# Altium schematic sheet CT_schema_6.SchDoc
size 278 x 170 mm
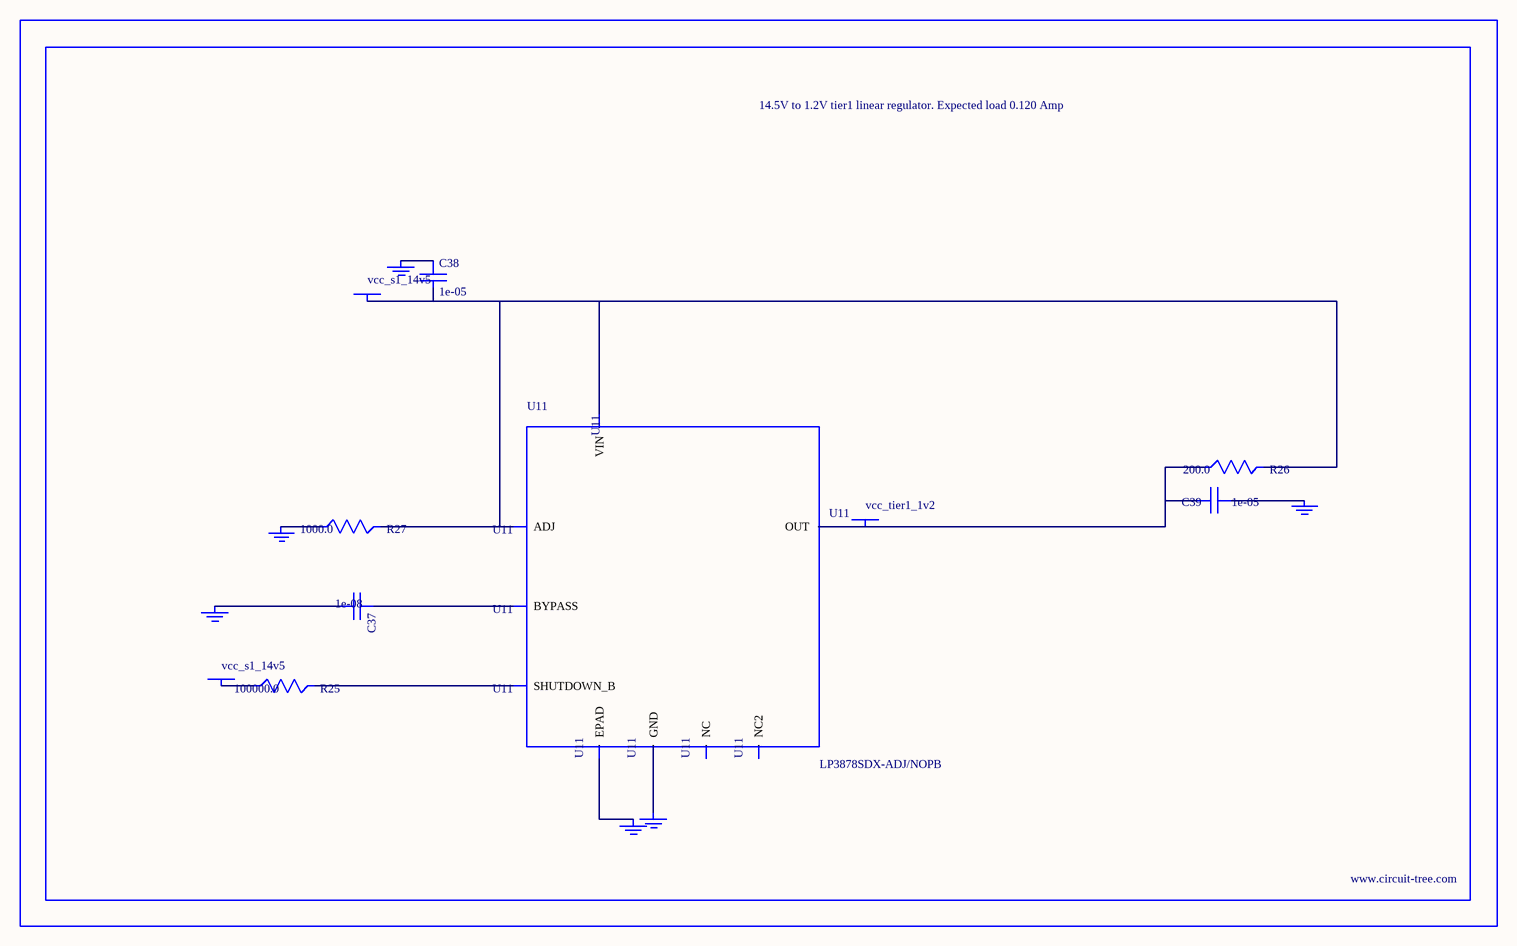
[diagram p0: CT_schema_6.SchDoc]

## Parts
BORDER5  (no value)
C37  1e-08  [C0402]
C38  1e-05  [C1210]
C39  1e-05  [C0805]
GND_INSTANCE_5_0  (no value)
GND_INSTANCE_5_1  (no value)
GND_INSTANCE_5_2  (no value)
GND_INSTANCE_5_3  (no value)
GND_INSTANCE_5_4  (no value)
GND_INSTANCE_5_5  (no value)
POWER_INSTANCE_5_0  vcc_s1_14v5
POWER_INSTANCE_5_1  vcc_s1_14v5
POWER_INSTANCE_5_2  vcc_tier1_1v2
R25  100000.0  [R0603]
R26  200.0  [R0603]
R27  1000.0  [R0603]
U11  LP3878SDX-ADJ/NOPB  [WSON-8]

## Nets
NetC37_1: C37.1 U11.1(BYPASS)
NetC37_2: C37.2 GND_INSTANCE_5_0.0(GND)
NetC38_1: C38.1 GND_INSTANCE_5_1.0(GND)
NetC38_2: C38.2 POWER_INSTANCE_5_0.0(PWR) R26.2 R27.2 U11.4(VIN) U11.6(ADJ)
NetC39_1: C39.1 GND_INSTANCE_5_2.0(GND)
NetC39_2: C39.2 POWER_INSTANCE_5_2.0(PWR) R26.1 U11.5(OUT)
NetGND_INSTANCE_5_3_0: GND_INSTANCE_5_3.0(GND) R27.1
NetGND_INSTANCE_5_4_0: GND_INSTANCE_5_4.0(GND) U11.PAD(EPAD)
NetGND_INSTANCE_5_5_0: GND_INSTANCE_5_5.0(GND) U11.3(GND)
NetPOWER_INSTANCE_5_1_0: POWER_INSTANCE_5_1.0(PWR) R25.1
NetR25_2: R25.2 U11.8(SHUTDOWN_B)

Not connected (* = marked no-connect by the designer): U11 2(NC) 7(NC2)

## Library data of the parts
BORDER5 = BORDER_PAGE5
C37 = C0402C103K3RAC
C38 = C1210C106K5PACTU
C39 = GRM219R60J106ME19D
GND_INSTANCE_5_0-GND_INSTANCE_5_5 = GND
POWER_INSTANCE_5_0-POWER_INSTANCE_5_2 = PWR
R25 = RC0603JR-07100KL
R26 = RC0603JR-07200RL
R27 = RC0603JR-071KL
